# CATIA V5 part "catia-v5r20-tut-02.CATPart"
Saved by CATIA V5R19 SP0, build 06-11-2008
Part number: c04tut02
Material "Aluminium": density 2710 kg/m3, Young's modulus 7e+10 Pa, Poisson ratio 0.346, thermal expansion 2.36e-05 1/K
Material "Aluminium": density 2710 kg/m3, Young's modulus 7e+10 Pa, Poisson ratio 0.346, thermal expansion 2.36e-05 1/K
Bounding box of the stored display mesh (mm): x 0 to 30, y -110 to 110, z -120 to 120
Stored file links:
  D:\Shriniwas\v5_r19\Part files\c04\c04tut02.CATPart
  C:\Program Files (x86)\Dassault Systemes\B19\intel_a\startup\materials\Catalog.CATMaterial
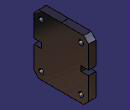
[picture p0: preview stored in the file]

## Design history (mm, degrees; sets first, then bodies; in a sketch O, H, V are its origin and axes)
Body1 (main body), material "Aluminium"
  Sketch1 on yz-plane, origin (0, 0, 0), H (0, 1, 0), V (0, 0, 1)
    construction line L1 (0, 0) -> (0, 117.7398)
    point P1 (0, 117.7398)
    axis line L2 (0, 0) -> (129.0807, 0)
    point P3 (0, 120)
    line L3 (0, 120) -> (90, 120)
    point P4 (90, 120)
    line L4 (90, 120) -> (110, 100)
    point P5 (110, 100)
    line L5 (110, 100) -> (110, 10)
    point P6 (110, 10)
    line L6 (110, 10) -> (80, 10)
    point P7 (80, 10)
    line L7 (80, 10) -> (80, 0)
    point P8 (80, 0)
    circle A1 centre (80, 90) radius 10
    point P9 (80, 90)
    point P10 (80, -10)
    point P11 (110, -10)
    line L8 (110, -10) -> (80, -10)
    point P12 (80, 0)
    line L9 (80, -10) -> (80, 0)
    point P13 (110, -100)
    line L10 (110, -100) -> (110, -10)
    circle A2 centre (80, -90) radius 10
    point P15 (90, -120)
    line L11 (90, -120) -> (110, -100)
    point P16 (0, -120)
    line L12 (0, -120) -> (90, -120)
    point P17 (0, -117.7398)
    point P18 (0, 0)
    construction line L13 (0, 0) -> (0, -117.7398)
    point P19 (-80, -10)
    point P20 (-110, -10)
    point P21 (-110, -100)
    point P23 (-90, -120)
    line L14 (-110, -10) -> (-80, -10)
    line L15 (-110, -100) -> (-110, -10)
    circle A3 centre (-80, -90) radius 10
    line L16 (-90, -120) -> (-110, -100)
    point P24 (0, -120)
    line L17 (0, -120) -> (-90, -120)
    point P25 (-80, 0)
    line L18 (-80, -10) -> (-80, 0)
    point P26 (-80, 0)
    point P27 (-80, 10)
    line L19 (-80, 10) -> (-80, 0)
    point P28 (-110, 10)
    line L20 (-110, 10) -> (-80, 10)
    point P29 (-110, 100)
    line L21 (-110, 100) -> (-110, 10)
    circle A4 centre (-80, 90) radius 10
    point P31 (-90, 120)
    line L22 (-90, 120) -> (-110, 100)
    point P32 (0, 120)
    line L23 (0, 120) -> (-90, 120)
    distance L15 L10 = 220
    distance L12 L3 = 240
    distance P9 L5 = 30
    distance P9 L3 = 30
    radius A1 = 10
    length L22 H = 20
    length L22 V = 20
    distance L8 L6 = 20
    distance L7 L19 = 160
    vertical: L1 V, L5 V, L7 V
    horizontal: L2 H, L3 H, L6 H
    coincidence: P3 L1, P8 L2, P3 P32, P8 P12, P16 P24, P25 P26
    symmetry: P7 P10 L2, P6 P11 L2, L6 L8 L2, P8 P12 L2, L7 L9 L2, P5 P13 L2, L5 L10 L2, A1 A2 L2, P4 P15 L2, L4 L11 L2, P3 P16 L2, L3 L12 L2, P1 P17 L2, O P18 L2, L1 L13 L2, P10 P19 L1, P11 P20 L1, P13 P21 L1, P15 P23 L1, L8 L14 L1, L10 L15 L1, A2 A3 L1, L11 L16 L1, P16 P24 L1, L12 L17 L1, P12 P25 L1, L9 L18 L1, P8 P26 L1, P7 P27 L1, L7 L19 L1, P6 P28 L1, L6 L20 L1, P5 P29 L1, L5 L21 L1, A1 A4 L1, P4 P31 L1, L4 L22 L1, P3 P32 L1, L3 L23 L1
  Pad1: profile Sketch1, direction (1, 0, 0), length 30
